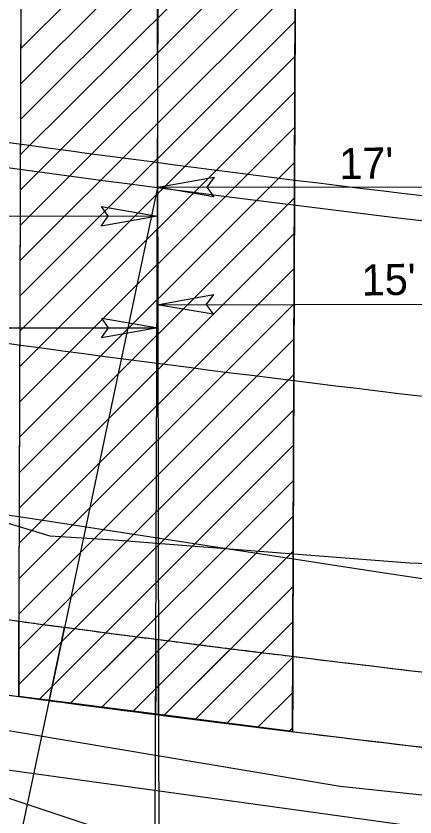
# Model space of a CAD drawing. Extents: x 1756964 to 1757438, y 736785 to 737067.
# Drawn here: x 1757129.59 to 1757145.61, y 736953.63 to 736985.8 of the extents above; entities that cross this region are included whole.
import ezdxf

# ---------------------------------------------------------------- set-up
doc = ezdxf.new("R2010")
doc.units = 0
for name, color, linetype in [('Exist Railroads Standard Gauge', 7, 'Continuous'), ('Exist Roads EOP', 7, 'Continuous'), ('Exist Utilities Gas UG Line SUE LOS B', 7, 'Continuous'), ('Exist Utilities Power UG Cable SUE LOS B', 7, 'Continuous'), ('Exist Utilities TV UG Cable SUE LOS C', 7, 'Continuous'), ('Exist Utilities Water UG Line SUE LOS B', 7, 'Continuous'), ('Old_Level_3', 7, 'Continuous'), ('Old_Level_7', 7, 'Continuous'), ('Prop Dimension', 7, 'Continuous'), ('Prop Horizontal Alignment Tick Label', 7, 'Continuous'), ('Prop Lane Lines', 7, 'Continuous'), ('Prop Paved Shoulder', 7, 'Continuous'), ('Prop Shade Light', 7, 'Continuous'), ('Prop Terminator CELL', 7, 'Continuous'), ('Sheet Plan CELL', 7, 'Continuous')]:
    doc.layers.add(name, color=color, linetype=linetype)

msp = doc.modelspace()

# ---------------------------------------------------------------- linework, layer by layer
at = {"layer": 'Exist Railroads Standard Gauge'}
msp.add_lwpolyline([(1757135.242, 736995.205), (1757135.341, 736944.111), (1757135.323, 736924.976)], dxfattribs=at)
at = {"layer": 'Exist Roads EOP'}
msp.add_lwpolyline([(1757018.66, 736985.696), (1757034.949, 736983.037), (1757061.196, 736978.712), (1757085.734, 736974.36), (1757105.946, 736970.789), (1757114.403, 736969.43), (1757118.624, 736967.486), (1757127.326, 736966.028), (1757130.944, 736964.921), (1757133.515, 736964.759), (1757145.39, 736963.846), (1757152.18, 736963.586), (1757158.454, 736963.047), (1757166.236, 736962.175), (1757173.047, 736961.847), (1757183.796, 736960.95), (1757193.006, 736960.371), (1757202.727, 736959.898), (1757211.305, 736959.577), (1757218.949, 736959.398), (1757227.166, 736959.341), (1757236.822, 736959.378), (1757246.473, 736959.28), (1757253.513, 736959.151)], dxfattribs=at)
at = {"layer": 'Exist Utilities Gas UG Line SUE LOS B'}
msp.add_lwpolyline([(1757018.66, 736980.427), (1757020.741, 736980.081), (1757042.541, 736977.085), (1757064.687, 736974.093), (1757082.004, 736971.657), (1757106.392, 736968.336), (1757118.551, 736967.356), (1757130.42, 736965.595), (1757143.948, 736963.504), (1757160.852, 736960.964), (1757176.571, 736959.225), (1757194.78, 736957.329), (1757214.425, 736955.424), (1757232.801, 736954.564), (1757250.556, 736954.418), (1757256.718, 736954.911)], dxfattribs=at)
at = {"layer": 'Exist Utilities Power UG Cable SUE LOS B'}
msp.add_lwpolyline([(1757121.288, 736955.918), (1757129.139, 736954.447), (1757143.687, 736949.59), (1757148.982, 736947.317), (1757150.787, 736946.665), (1757151.443, 736943.689), (1757152.452, 736940.225), (1757153.984, 736937.601), (1757157.324, 736934.588), (1757161.381, 736931.58)], dxfattribs=at)
at = {"layer": 'Exist Utilities TV UG Cable SUE LOS C'}
msp.add_lwpolyline([(1757018.66, 736970.876), (1757022.572, 736970.301), (1757163.65, 736950.76), (1757199.713, 736947.976), (1757242.132, 736949.17), (1757245.371, 736949.087), (1757247.9, 736948.084)], dxfattribs=at)
at = {"layer": 'Exist Utilities Water UG Line SUE LOS B'}
msp.add_lwpolyline([(1757110.311, 736959.486), (1757116.978, 736958.523), (1757128.166, 736957.293), (1757142.608, 736954.867), (1757160.324, 736952.992)], dxfattribs=at)
at = {"layer": 'Old_Level_3'}
msp.add_line((1757135.271, 736978.916), (1757125.173, 736931.074), dxfattribs=at)
at = {"layer": 'Old_Level_7'}
for p, q in [((1757129.7, 736958.47), (1757129.827, 736994.787)), ((1757129.791, 736984.495), (1757138.878, 736993.582)), ((1757129.786, 736983.076), (1757140.126, 736993.416)), ((1757140.695, 736957.061), (1757140.822, 736993.324)), ((1757129.781, 736981.657), (1757140.82, 736992.695)), ((1757129.776, 736980.237), (1757140.815, 736991.276)), ((1757129.771, 736978.818), (1757140.81, 736989.857)), ((1757129.766, 736977.399), (1757140.805, 736988.438)), ((1757129.761, 736975.98), (1757140.8, 736987.019)), ((1757129.756, 736974.561), (1757140.795, 736985.599)), ((1757129.751, 736973.141), (1757140.79, 736984.18)), ((1757129.746, 736971.722), (1757140.785, 736982.761)), ((1757129.741, 736970.303), (1757140.78, 736981.342)), ((1757129.736, 736968.884), (1757140.775, 736979.923)), ((1757129.731, 736967.465), (1757140.77, 736978.503)), ((1757129.726, 736966.045), (1757140.765, 736977.084)), ((1757129.721, 736964.626), (1757140.76, 736975.665)), ((1757129.716, 736963.207), (1757140.755, 736974.246)), ((1757129.711, 736961.788), (1757140.75, 736972.827)), ((1757129.706, 736960.369), (1757140.745, 736971.408)), ((1757129.701, 736958.95), (1757140.74, 736969.988)), ((1757130.53, 736958.364), (1757140.735, 736968.569)), ((1757131.783, 736958.203), (1757140.73, 736967.15)), ((1757133.037, 736958.042), (1757140.725, 736965.731)), ((1757134.29, 736957.882), (1757140.72, 736964.312)), ((1757135.544, 736957.721), (1757140.715, 736962.892)), ((1757136.797, 736957.56), (1757140.71, 736961.473)), ((1757138.051, 736957.4), (1757140.705, 736960.054)), ((1757139.304, 736957.239), (1757140.7, 736958.635)), ((1757140.558, 736957.078), (1757140.695, 736957.216))]:
    msp.add_line(p, q, dxfattribs=at)
msp.add_lwpolyline([(1757129.827, 736994.787), (1757140.822, 736993.324), (1757140.695, 736957.061), (1757129.7, 736958.47)], close=True, dxfattribs=at)
msp.add_arc((1757258.672, 737920.867), 971, 262.367153, 263.021256, dxfattribs=at)
at = {"layer": 'Prop Dimension'}
for p, q in [((1757135.279, 736978.924), (1757152.279, 736978.958)), ((1757135.267, 736977.769), (1757120.267, 736977.74)), ((1757135.255, 736974.208), (1757150.255, 736974.237)), ((1757118.284, 736973.253), (1757135.284, 736973.286))]:
    msp.add_line(p, q, dxfattribs=at)
at = {"layer": 'Prop Horizontal Alignment Tick Label'}
msp.add_line((1757135.082, 736924.976), (1757135.474, 737036.72), dxfattribs=at)
at = {"layer": 'Prop Lane Lines'}
for radius in [949, 957]:
    msp.add_arc((1757258.672, 737920.867), radius, 261.751158, 263.379564, dxfattribs=at)
at = {"layer": 'Prop Paved Shoulder'}
msp.add_arc((1757258.672, 737920.867), 971, 261.751158, 263.379564, dxfattribs=at)
at = {"layer": 'Prop Shade Light'}
for p, q in [((1757129.71, 736961.496), (1757129.706, 736960.369)), ((1757129.706, 736960.369), (1757130.701, 736961.363)), ((1757130.701, 736961.363), (1757129.706, 736960.369)), ((1757133.199, 736961.033), (1757131.041, 736958.875)), ((1757131.041, 736958.875), (1757133.199, 736961.033)), ((1757131.419, 736960.668), (1757131.543, 736961.251)), ((1757131.543, 736961.251), (1757131.419, 736960.668)), ((1757131.949, 736961.197), (1757131.419, 736960.668)), ((1757131.419, 736960.668), (1757131.949, 736961.197)), ((1757129.701, 736958.95), (1757131.419, 736960.668)), ((1757131.419, 736960.668), (1757129.701, 736958.95)), ((1757131.041, 736958.875), (1757131.419, 736960.668)), ((1757131.419, 736960.668), (1757131.041, 736958.875)), ((1757131.783, 736958.203), (1757134.451, 736960.871)), ((1757134.451, 736960.871), (1757131.783, 736958.203)), ((1757135.206, 736960.211), (1757135.208, 736960.773)), ((1757135.208, 736960.773), (1757135.206, 736960.211)), ((1757135.31, 736960.315), (1757135.309, 736960.76)), ((1757135.309, 736960.76), (1757135.31, 736960.315)), ((1757135.704, 736960.709), (1757135.31, 736960.315)), ((1757135.31, 736960.315), (1757135.704, 736960.709)), ((1757129.706, 736960.369), (1757129.701, 736958.95)), ((1757135.31, 736960.315), (1757135.206, 736960.211)), ((1757135.206, 736960.211), (1757135.31, 736960.315)), ((1757135.31, 736960.315), (1757135.312, 736958.904)), ((1757135.312, 736958.904), (1757135.31, 736960.315)), ((1757136.958, 736960.549), (1757135.312, 736958.904)), ((1757135.312, 736958.904), (1757136.958, 736960.549)), ((1757135.544, 736957.721), (1757138.214, 736960.391)), ((1757138.214, 736960.391), (1757135.544, 736957.721)), ((1757133.037, 736958.042), (1757135.206, 736960.211)), ((1757135.206, 736960.211), (1757133.037, 736958.042)), ((1757135.201, 736958.792), (1757135.206, 736960.211)), ((1757135.206, 736960.211), (1757135.201, 736958.792)), ((1757136.797, 736957.56), (1757139.471, 736960.234)), ((1757139.471, 736960.234), (1757136.797, 736957.56)), ((1757138.051, 736957.4), (1757140.705, 736960.054)), ((1757140.705, 736960.054), (1757138.051, 736957.4)), ((1757140.7, 736958.635), (1757140.705, 736960.054)), ((1757140.705, 736960.054), (1757140.705, 736960.082)), ((1757129.7, 736958.47), (1757129.701, 736958.95)), ((1757129.701, 736958.95), (1757129.7, 736958.47)), ((1757130.53, 736958.364), (1757131.041, 736958.875)), ((1757131.041, 736958.875), (1757130.53, 736958.364)), ((1757131.041, 736958.875), (1757130.922, 736958.314)), ((1757130.922, 736958.314), (1757131.041, 736958.875)), ((1757134.29, 736957.882), (1757135.201, 736958.792)), ((1757135.201, 736958.792), (1757134.29, 736957.882)), ((1757135.197, 736957.766), (1757135.201, 736958.792)), ((1757135.201, 736958.792), (1757135.197, 736957.766)), ((1757135.312, 736958.904), (1757135.201, 736958.792)), ((1757135.201, 736958.792), (1757135.312, 736958.904)), ((1757135.312, 736958.904), (1757135.315, 736957.75)), ((1757135.315, 736957.75), (1757135.312, 736958.904)), ((1757129.7, 736958.47), (1757130.53, 736958.364)), ((1757130.53, 736958.364), (1757130.922, 736958.314)), ((1757139.304, 736957.239), (1757140.7, 736958.635)), ((1757140.7, 736958.635), (1757139.304, 736957.239)), ((1757140.7, 736958.635), (1757140.695, 736957.216)), ((1757140.695, 736957.216), (1757140.7, 736958.635)), ((1757130.922, 736958.314), (1757131.783, 736958.203)), ((1757131.783, 736958.203), (1757133.037, 736958.042)), ((1757133.037, 736958.042), (1757134.29, 736957.882)), ((1757134.29, 736957.882), (1757135.197, 736957.766)), ((1757135.197, 736957.766), (1757135.315, 736957.75)), ((1757135.315, 736957.75), (1757135.544, 736957.721)), ((1757135.544, 736957.721), (1757136.797, 736957.56)), ((1757136.797, 736957.56), (1757138.051, 736957.4)), ((1757138.051, 736957.4), (1757139.304, 736957.239)), ((1757139.304, 736957.239), (1757140.558, 736957.078)), ((1757140.558, 736957.078), (1757140.695, 736957.216)), ((1757140.695, 736957.216), (1757140.558, 736957.078)), ((1757140.558, 736957.078), (1757140.695, 736957.061)), ((1757140.695, 736957.216), (1757140.695, 736957.061)), ((1757140.695, 736957.061), (1757140.695, 736957.216))]:
    msp.add_line(p, q, dxfattribs=at)
for points in [[(1757129.701, 736958.95), (1757129.706, 736960.369), (1757129.71, 736961.496)], [(1757140.705, 736960.082), (1757140.705, 736960.054), (1757140.7, 736958.635)]]:
    msp.add_lwpolyline(points, dxfattribs=at)
for radius, start, end in [(968, 261.751158, 263.379564), (968, 261.904156, 262.343989), (968, 262.343989, 262.40314), (968, 262.40314, 262.453412), (968, 262.453412, 262.477688), (968, 262.477688, 262.55231), (968, 262.55231, 262.627007), (968, 262.627007, 262.672188), (968, 262.672188, 262.678218), (968, 262.678218, 262.701779), (968, 262.701779, 262.776627), (968, 262.776627, 262.851551), (968, 262.851551, 262.92655), (968, 262.92655, 263.000151), (968, 263.000151, 263.379564), (971, 261.926769, 262.367153), (971, 263.021256, 263.379564)]:
    msp.add_arc((1757258.672, 737920.867), radius, start, end, dxfattribs=at)
at = {"layer": 'Prop Terminator CELL'}
for points in [[(1757137.53, 736978.541), (1757135.279, 736978.924), (1757137.541, 736979.329), (1757137.254, 736978.928)], [(1757133.017, 736978.152), (1757135.267, 736977.769), (1757133.006, 736977.364), (1757133.292, 736977.765)], [(1757137.506, 736973.825), (1757135.255, 736974.208), (1757137.517, 736974.612), (1757137.23, 736974.212)], [(1757133.034, 736973.67), (1757135.284, 736973.286), (1757133.023, 736972.882), (1757133.309, 736973.283)]]:
    msp.add_lwpolyline(points, close=True, dxfattribs=at)
at = {"layer": 'Sheet Plan CELL'}
msp.add_arc((1757258.672, 737920.867), 950, 260.677533, 269.882134, dxfattribs=at)

# ---------------------------------------------------------------- texts
at = {"layer": 'Prop Dimension'}
for s, p in [("17'", (1757142.576, 736979.248)), ("15'", (1757143.471, 736974.572))]:
    msp.add_text(s, height=1.25, rotation=1.0157, dxfattribs=at).set_placement(p)

doc.saveas('drawing.dxf')
